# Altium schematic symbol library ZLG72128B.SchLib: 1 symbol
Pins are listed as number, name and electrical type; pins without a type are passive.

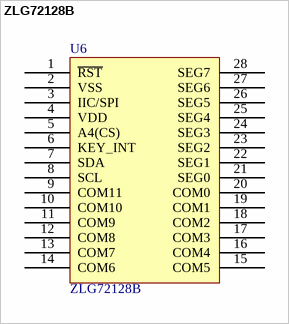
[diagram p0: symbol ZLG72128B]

## ZLG72128B
designator U6
footprint Model Name (Footprint not found)
footprint TSOP65P640X110-28N (TSOP, 28-Leads, Body 9.8x4.5mm (max), Pitch 0.65mm, IPC Medium Density)
pins: 1 ~{RST}, 2 VSS, 3 IIC/SPI, 4 VDD, 5 A4(CS), 6 KEY_INT, 7 SDA, 8 SCL, 9 COM11, 10 COM10, 11 COM9, 12 COM8, 13 COM7, 14 COM6, 15 COM5, 16 COM4, 17 COM3, 18 COM2, 19 COM1, 20 COM0, 21 SEG0, 22 SEG1, 23 SEG2, 24 SEG3, 25 SEG4, 26 SEG5, 27 SEG6, 28 SEG7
